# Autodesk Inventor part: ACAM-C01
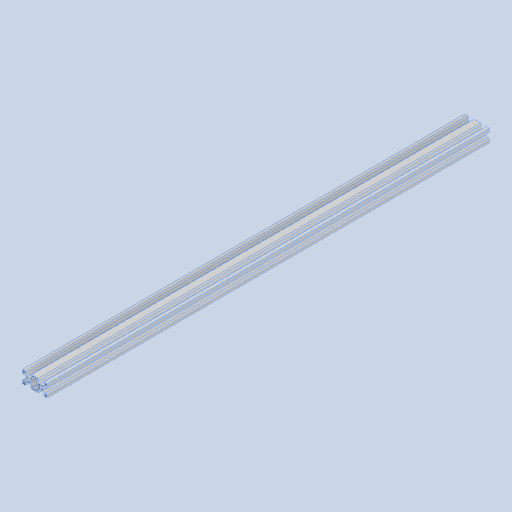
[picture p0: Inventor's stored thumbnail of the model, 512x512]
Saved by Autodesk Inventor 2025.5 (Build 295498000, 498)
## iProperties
Created: 2019-07
Part Number: ACAM-C01
Material: SOLIDWORKS Materials|6063-T5
Document SubType Name: Modeling
Designer: Luis M
Density: 2.7 g/cm^3
Appearance: blue anodized aluminum
Description: Perfil V-Slot 2040 × 700
Sending System: SolidWorks 2018
Last Author: Danish
Last Saved: 2020-09-29
Material_BOM: Aluminio
Proceso_BOM: Comercial
Author: Luis M
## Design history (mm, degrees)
fillet "Fillet1"
sketch "Boceto1"
  geometry: L1 (-15.1, 4.9)-(-15.1, 0.5) reference; L2 (-14.6, 0)-(-10.2, 0) reference; L3 (-10.2, 0)-(-8.2, 2) reference; L4 (-8.2, 2)-(-10.6, 2) reference; L5 (-10.6, 2)-(-10.6, 3.439) reference; L6 (-10.6, 3.439)-(-7.639, 6.4) reference; L7 (-7.639, 6.4)-(-2.561, 6.4) reference; L8 (-2.561, 6.4)-(0.4, 3.439) reference; L9 (0.4, 3.439)-(0.4, 2) reference; L10 (0.4, 2)-(-2, 2) reference; L11 (-2, 2)-(0, 0) reference; L12 (0, 0)-(10.214, 0) reference; L13 (10.214, 0)-(12.214, 2) reference; L14 (12.214, 2)-(9.4, 2) reference; L15 (9.4, 2)-(9.4, 3.439) reference; L16 (9.4, 3.439)-(12.361, 6.4) reference; L17 (12.361, 6.4)-(17.439, 6.4) reference; L18 (17.439, 6.4)-(20.4, 3.439) reference; L19 (20.4, 3.439)-(20.4, 2) reference; L20 (20.4, 2)-(18.414, 2) reference; L21 (18.414, 2)-(20, 0) reference; L22 (20, 0)-(24.4, 0) reference; L23 (24.9, 0.5)-(24.9, 4.9) reference; L24 (24.9, 4.9)-(22.9, 6.9) reference; L25 (22.9, 6.9)-(22.9, 4.5) reference; L26 (22.9, 4.5)-(21.461, 4.5) reference; L27 (21.461, 4.5)-(18.5, 7.461) reference; L28 (18.5, 7.461)-(18.5, 12.539) reference; L29 (18.5, 12.539)-(21.461, 15.5) reference; L30 (21.461, 15.5)-(22.9, 15.5) reference; L31 (22.9, 15.5)-(22.9, 13.1) reference; L32 (22.9, 13.1)-(24.9, 15.1) reference; L33 (24.9, 15.1)-(24.9, 19.5) reference; L34 (24.4, 20)-(20, 20) reference; L35 (20, 20)-(18, 18) reference; L36 (18, 18)-(20.4, 18) reference; L37 (20.4, 18)-(20.4, 16.561) reference; L38 (20.4, 16.561)-(17.439, 13.6) reference; L39 (17.439, 13.6)-(12.361, 13.6) reference; L40 (12.361, 13.6)-(9.4, 16.561) reference; L41 (9.4, 16.561)-(9.4, 18) reference; L42 (9.4, 18)-(12.214, 18) reference; L43 (12.214, 18)-(10.214, 20) reference; L44 (10.214, 20)-(0, 20) reference; L45 (0, 20)-(-2, 18) reference; L46 (-2, 18)-(0.4, 18) reference; L47 (0.4, 18)-(0.4, 16.561) reference; L48 (0.4, 16.561)-(-2.561, 13.6) reference; L49 (-2.561, 13.6)-(-7.639, 13.6) reference; L50 (-7.639, 13.6)-(-10.6, 16.561) reference; L51 (-10.6, 16.561)-(-10.6, 18) reference; L52 (-10.6, 18)-(-8.2, 18) reference; L53 (-8.2, 18)-(-10.2, 20) reference; L54 (-10.2, 20)-(-14.6, 20) reference; L55 (-15.1, 19.5)-(-15.1, 15.1) reference; L56 (-15.1, 15.1)-(-13.1, 13.1) reference; L57 (-13.1, 13.1)-(-13.1, 15.5) reference; L58 (-13.1, 15.5)-(-11.661, 15.5) reference; L59 (-11.661, 15.5)-(-8.7, 12.539) reference; L60 (-8.7, 12.539)-(-8.7, 7.461) reference; L61 (-8.7, 7.461)-(-11.661, 4.5) reference; L62 (-11.661, 4.5)-(-13.1, 4.5) reference; L63 (-13.1, 4.5)-(-13.1, 6.9) reference; L64 (-13.1, 6.9)-(-15.1, 4.9) reference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; C1 r 2.1 at (-5.1, 10) reference; C2 r 2.1 at (14.9, 10) reference; A1 r 0.5 centre (-14.6, 0.5) between (-15.1, 0.5) and (-14.6, 0) reference; A2 r 0.5 centre (24.4, 0.5) between (24.4, 0) and (24.9, 0.5) reference; A3 r 0.5 centre (24.4, 19.5) between (24.9, 19.5) and (24.4, 20) reference; A4 r 0.5 centre (-14.6, 19.5) between (-14.6, 20) and (-15.1, 19.5) reference; 1 further point
extrude "Extrusión1" join sketch "Boceto1" distance "d0" = 300; taper "d1" = 0 deg
node "Sólido1"
node "Contorno proyectado1"
